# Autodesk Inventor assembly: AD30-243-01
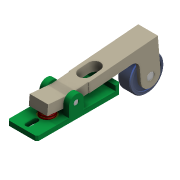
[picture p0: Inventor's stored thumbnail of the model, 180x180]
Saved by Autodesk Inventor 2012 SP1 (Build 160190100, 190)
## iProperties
Shininess: 0.0
Created: 2000-07
Part Number: AD30-243-01
Description: DETENT ASSEMBLY
Document SubType Name: Assembly
Designer: Ron
Density: 0.0
Volumn: 0.0
Area: 0.0
PropertySet Name: Model Information
Control State: 0
Master: False
Checked Out: False
Title: DETENT ASM
Author: Ron
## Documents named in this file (10)
- D:\AOTC\Autodesk Inventor 2012 Essential for New Users\Autodesk Inventor 2011 Esentials - Project Files\Learning\Workspace\Sub-Assemblies\detent.iam
- D:\AOTC\Autodesk Inventor 2012 Essential for New Users\Autodesk Inventor 2011 Esentials - Project Files\Learning\Workspace\Parts\detent bracket.ipt
- D:\AOTC\Autodesk Inventor 2012 Essential for New Users\Autodesk Inventor 2011 Esentials - Project Files\Learning\Workspace\Parts\detent pivot mount.ipt
- D:\AOTC\Autodesk Inventor 2012 Essential for New Users\Autodesk Inventor 2011 Esentials - Project Files\Learning\Workspace\Libraries\Content Center Files\en-US\BA97DF0F-B3F9-031B-C86A-A432CA559196.ipt
- D:\AOTC\Autodesk Inventor 2012 Essential for New Users\Autodesk Inventor 2011 Esentials - Project Files\Learning\Workspace\Libraries\Content Center Files\en-US\9ECBB5A1-AADB-6BAA-27F0-96D7996E1213.ipt
- D:\AOTC\Autodesk Inventor 2012 Essential for New Users\Autodesk Inventor 2011 Esentials - Project Files\Learning\Workspace\Parts\detent roller.ipt
- D:\AOTC\Autodesk Inventor 2012 Essential for New Users\Autodesk Inventor 2011 Esentials - Project Files\Learning\Workspace\Parts\LC-038E-6.ipt
- D:\AOTC\Autodesk Inventor 2012 Essential for New Users\Autodesk Inventor 2011 Esentials - Project Files\Learning\Workspace\Parts\detent roller-01.ipt
- detent-01.iam
- detent-02.iam
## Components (6 placed, 6 different names)
1. detent pivot mount:1 — Insert:1, Insert:3, Flush:2, Flush:3, Mate:3
2. Pin - Hardened Ground Production Dowel - 3/16 x 1/2:1 — Insert:2, Mate:2
3. Pin - Hardened Ground Production Dowel - 1/8 x 3/4:1 — Insert:1
4. detent bracket:1 — Insert:2, Insert:3
5. detent roller-01:1 — Flush:2, Mate:2
6. LC-038E-6:1 — Flush:3, Mate:3
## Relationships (7: Insert 3, Flush 2, Mate 2)
- Insert:1: detent pivot mount:1 ↔ Pin - Hardened Ground Production Dowel - 1/8 x 3/4:1
- Insert:2: Pin - Hardened Ground Production Dowel - 3/16 x 1/2:1 ↔ detent bracket:1
- Insert:3: detent pivot mount:1 ↔ detent bracket:1
- Flush:2: detent pivot mount:1 ↔ detent roller-01:1
- Mate:2: Pin - Hardened Ground Production Dowel - 3/16 x 1/2:1 ↔ detent roller-01:1
- Flush:3: detent pivot mount:1 ↔ LC-038E-6:1
- Mate:3: detent pivot mount:1 ↔ LC-038E-6:1
